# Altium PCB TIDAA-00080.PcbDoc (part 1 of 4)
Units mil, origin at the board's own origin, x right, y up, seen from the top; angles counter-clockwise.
Board outline 7874.02 x 2559.06 mil, 4 copper layers (Top Layer, MidLayer1, MidLayer2, Bottom Layer), stack 61.2 mil thick; 363 components, 169 nets, 940 pads, 199 vias.
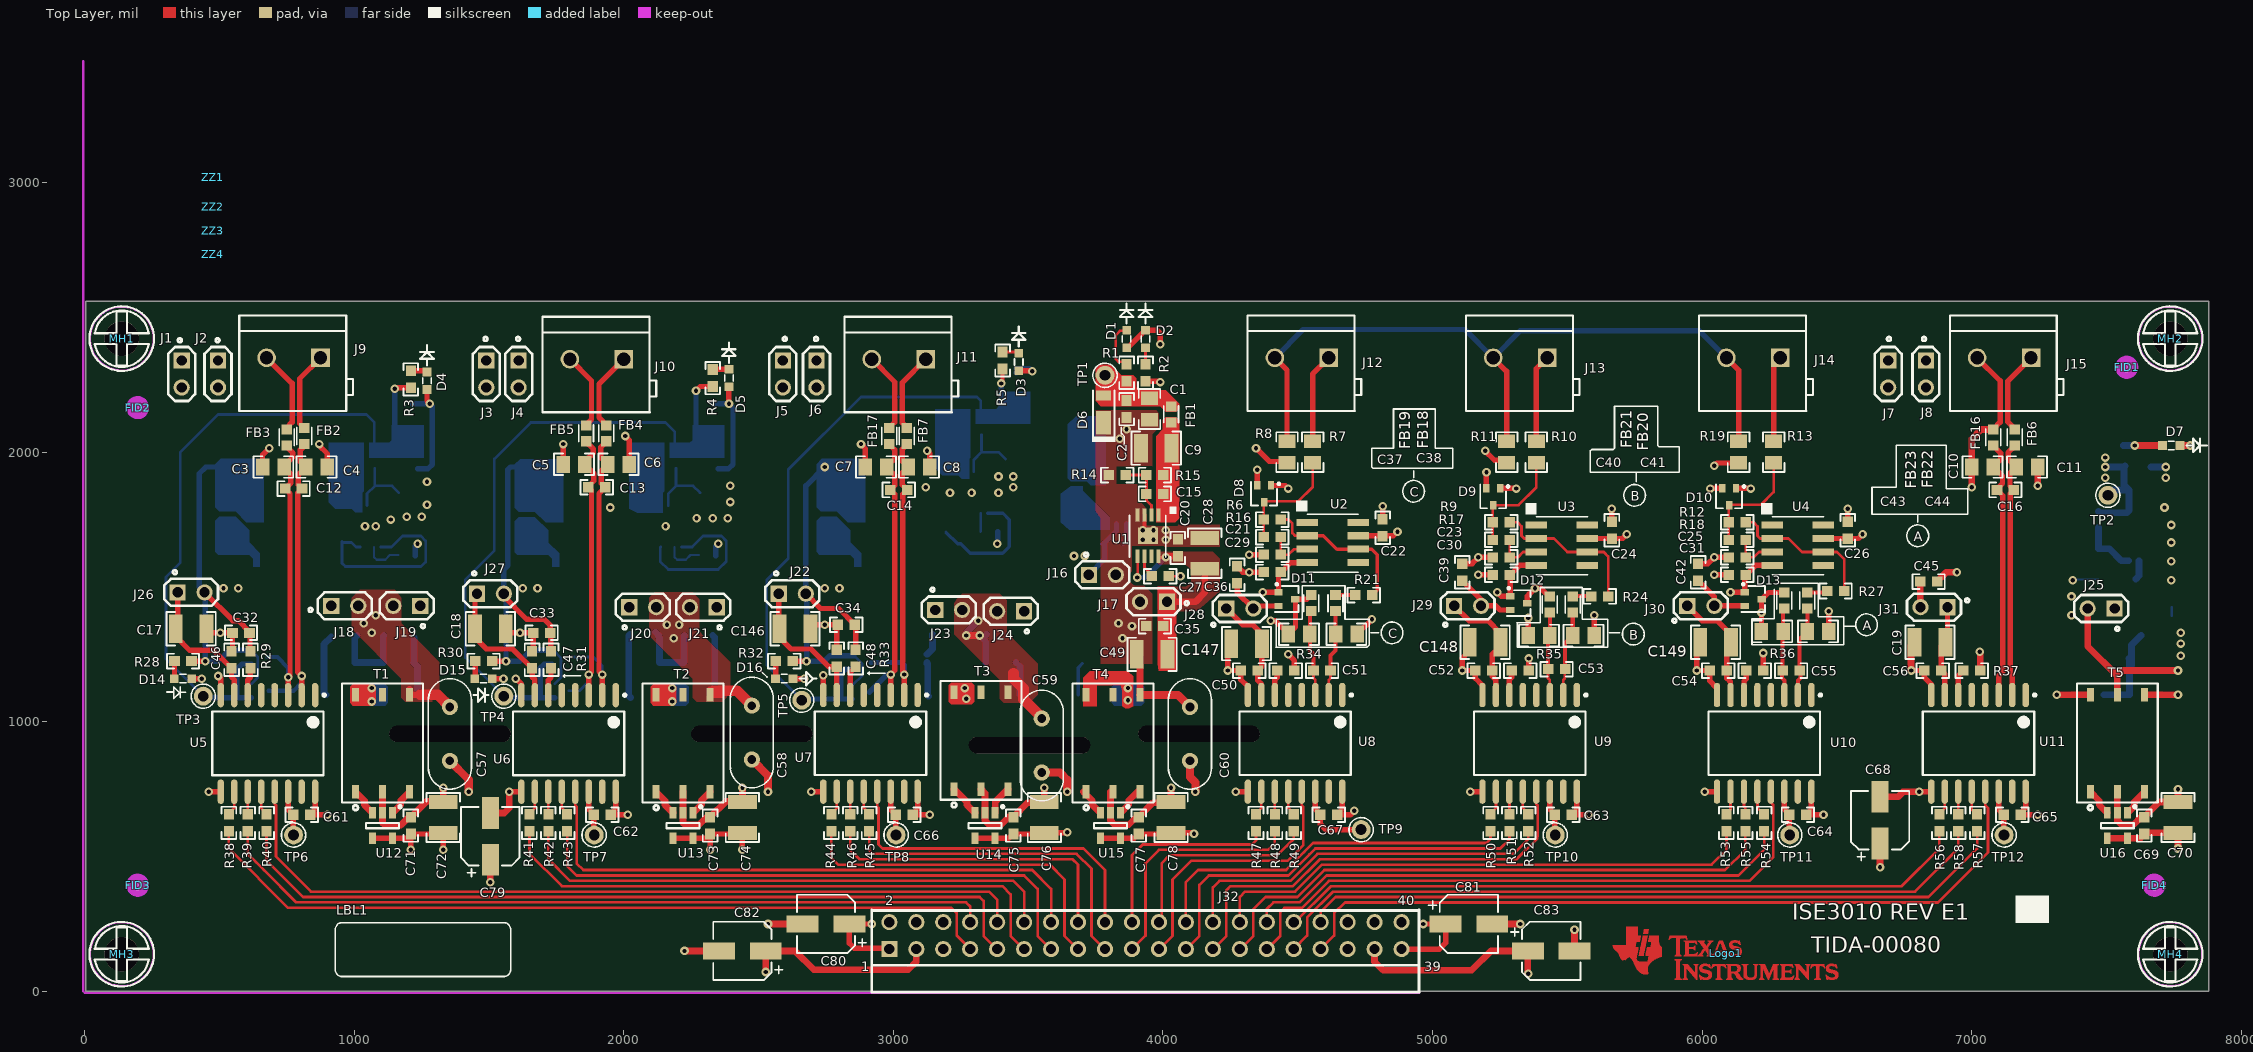
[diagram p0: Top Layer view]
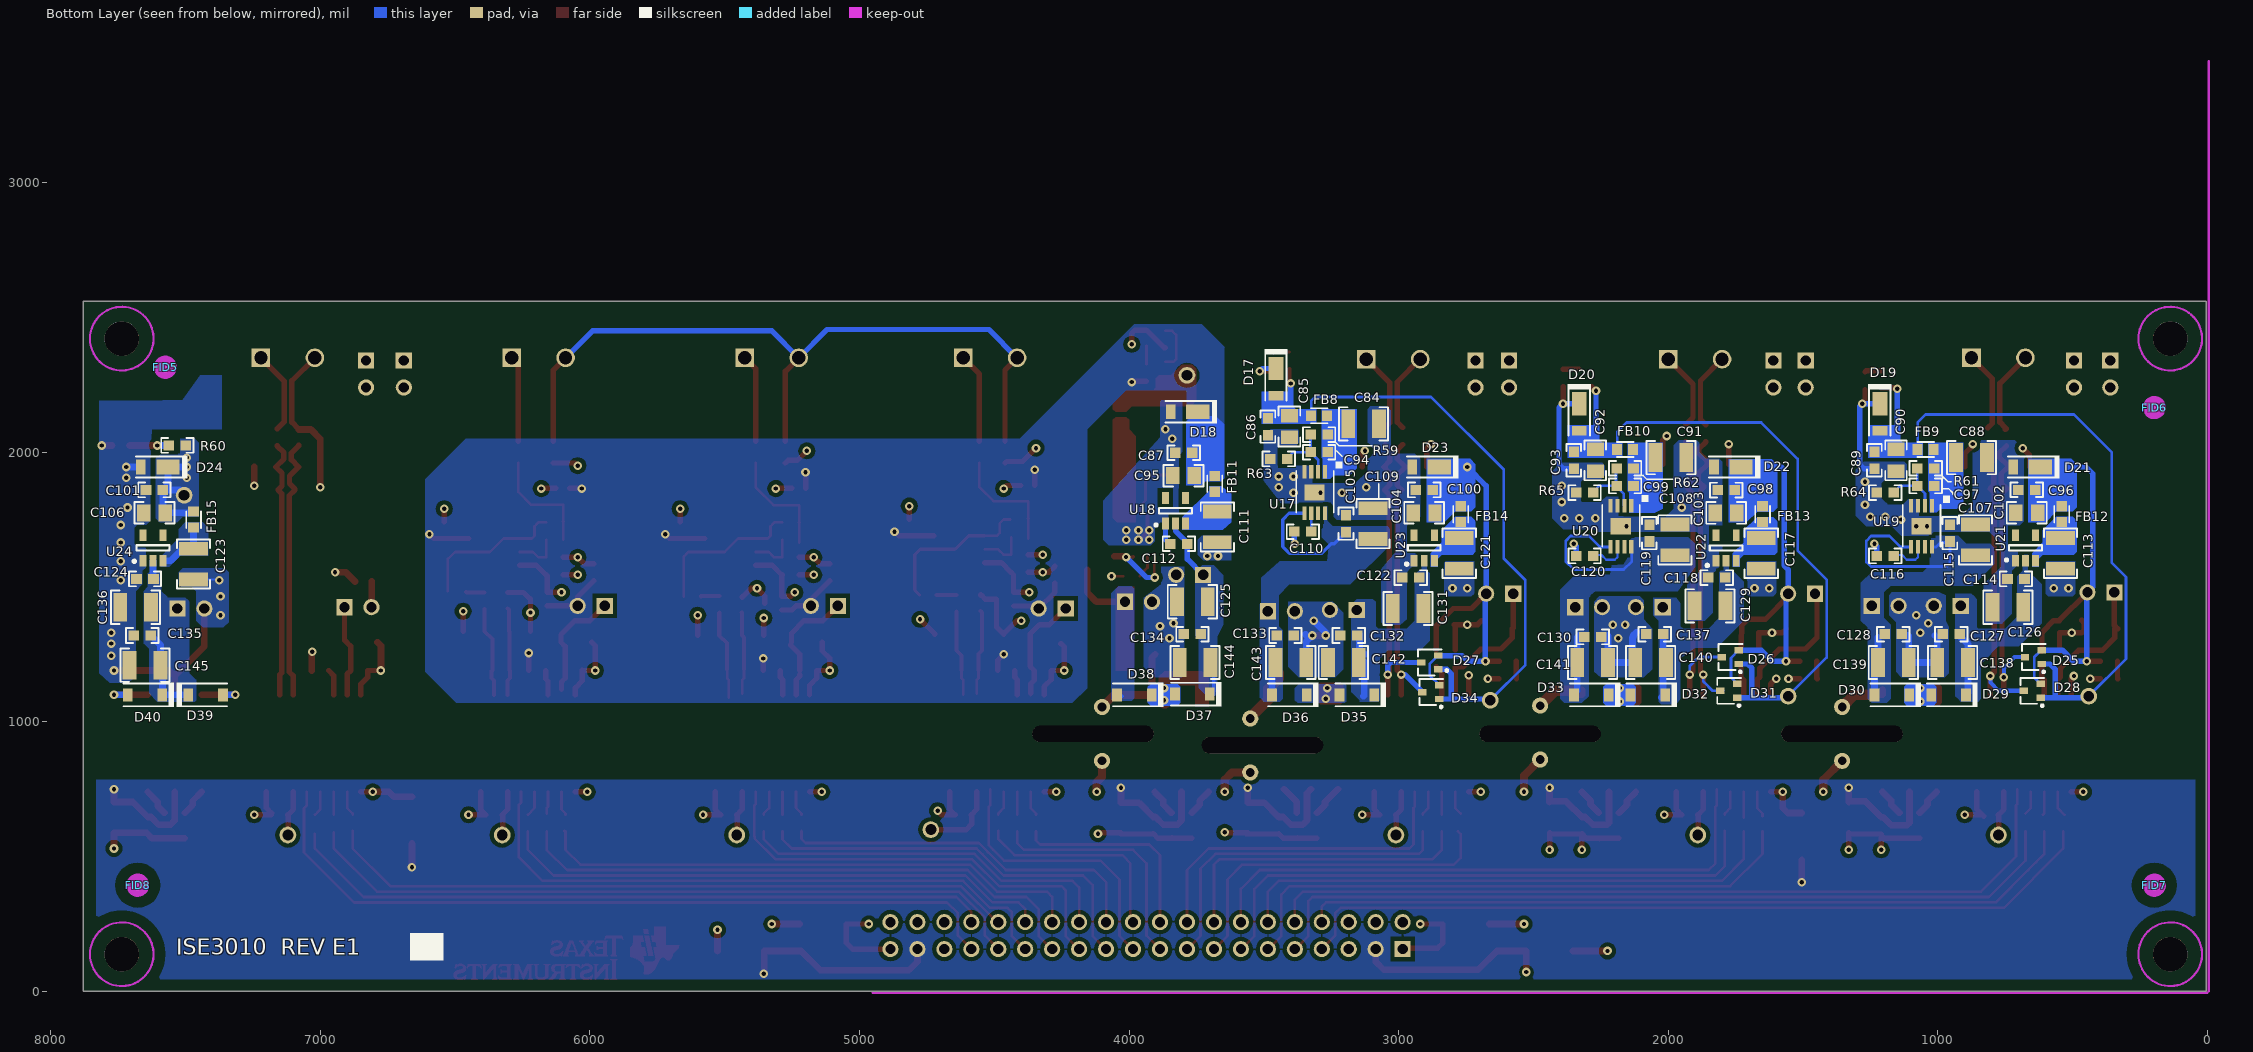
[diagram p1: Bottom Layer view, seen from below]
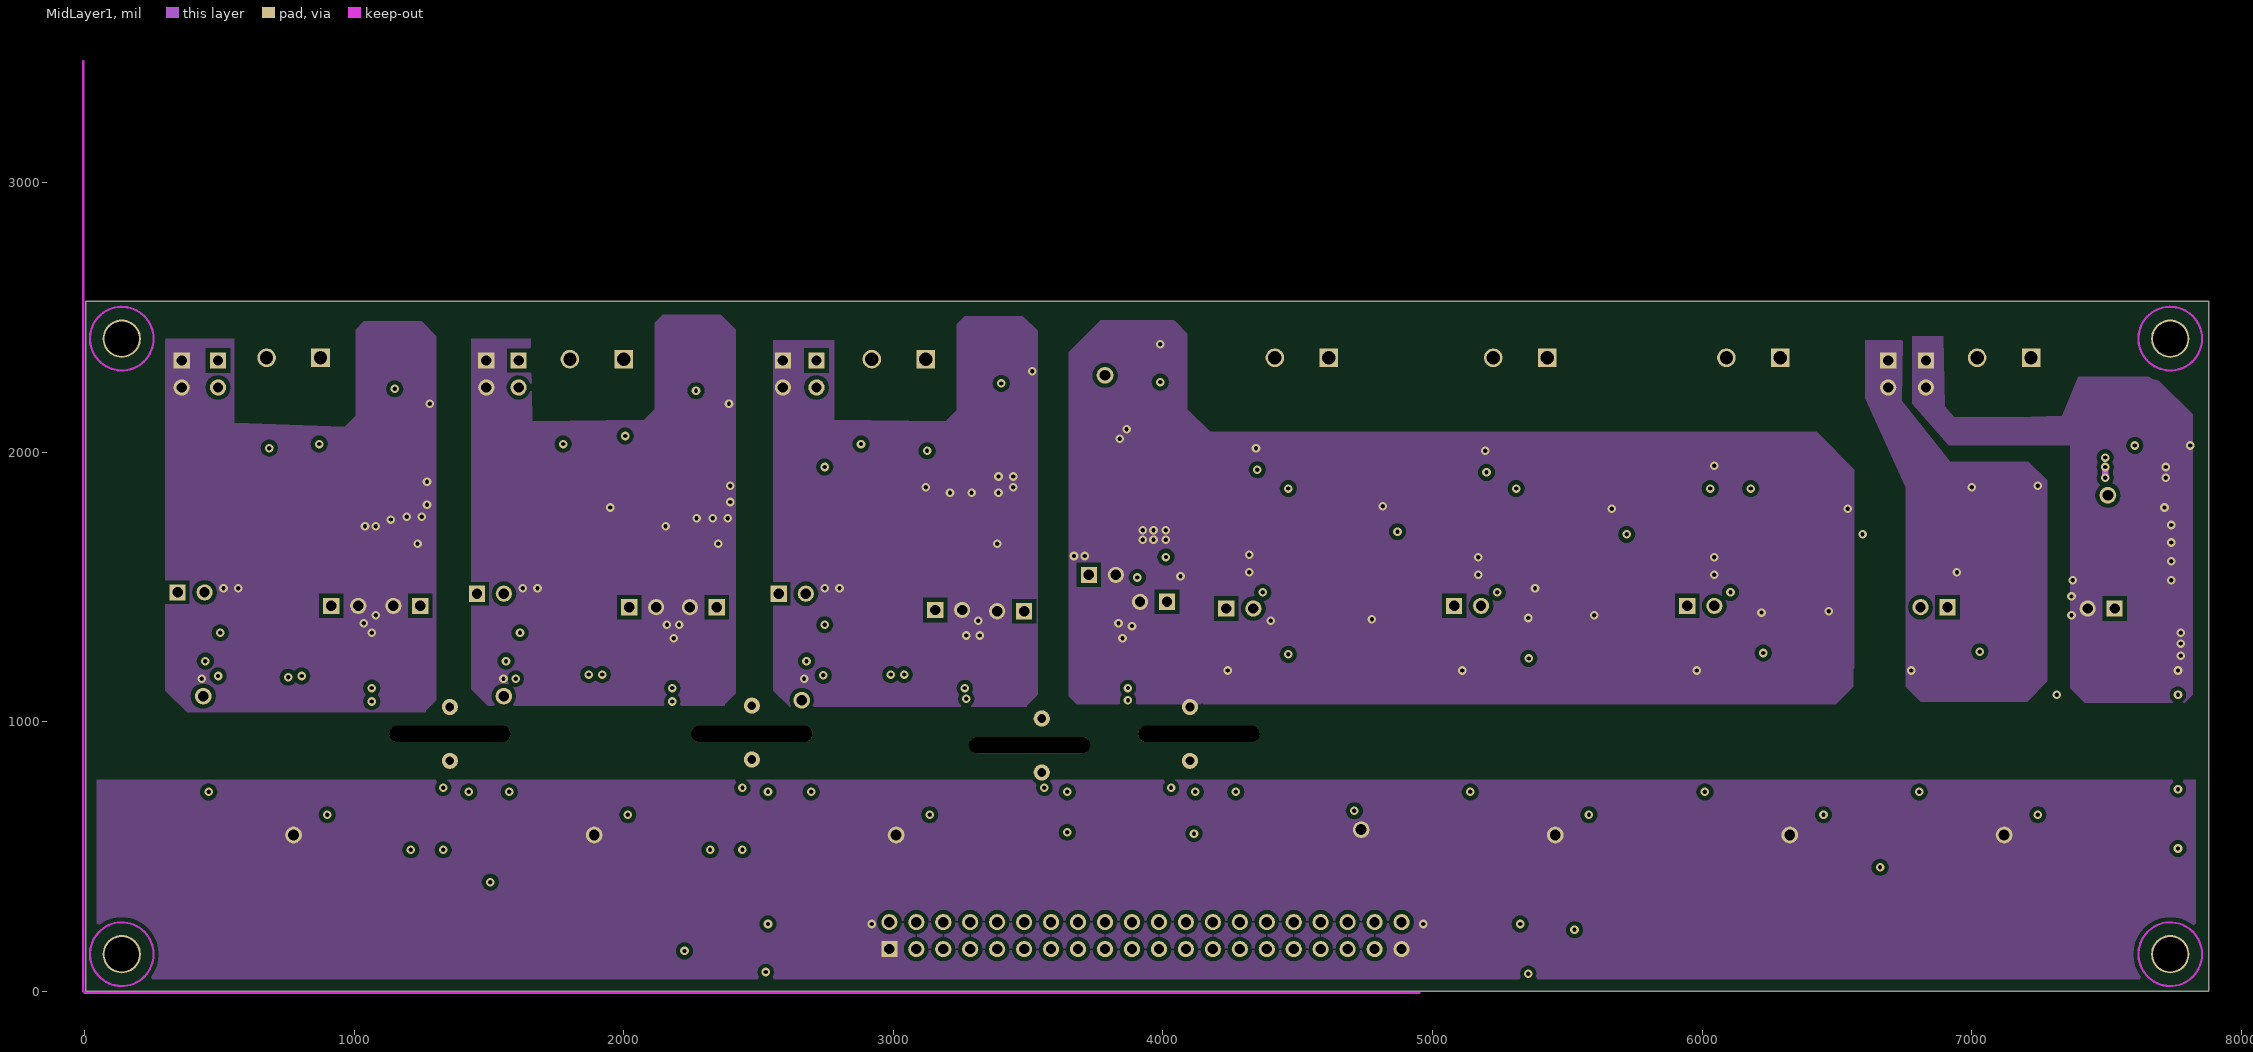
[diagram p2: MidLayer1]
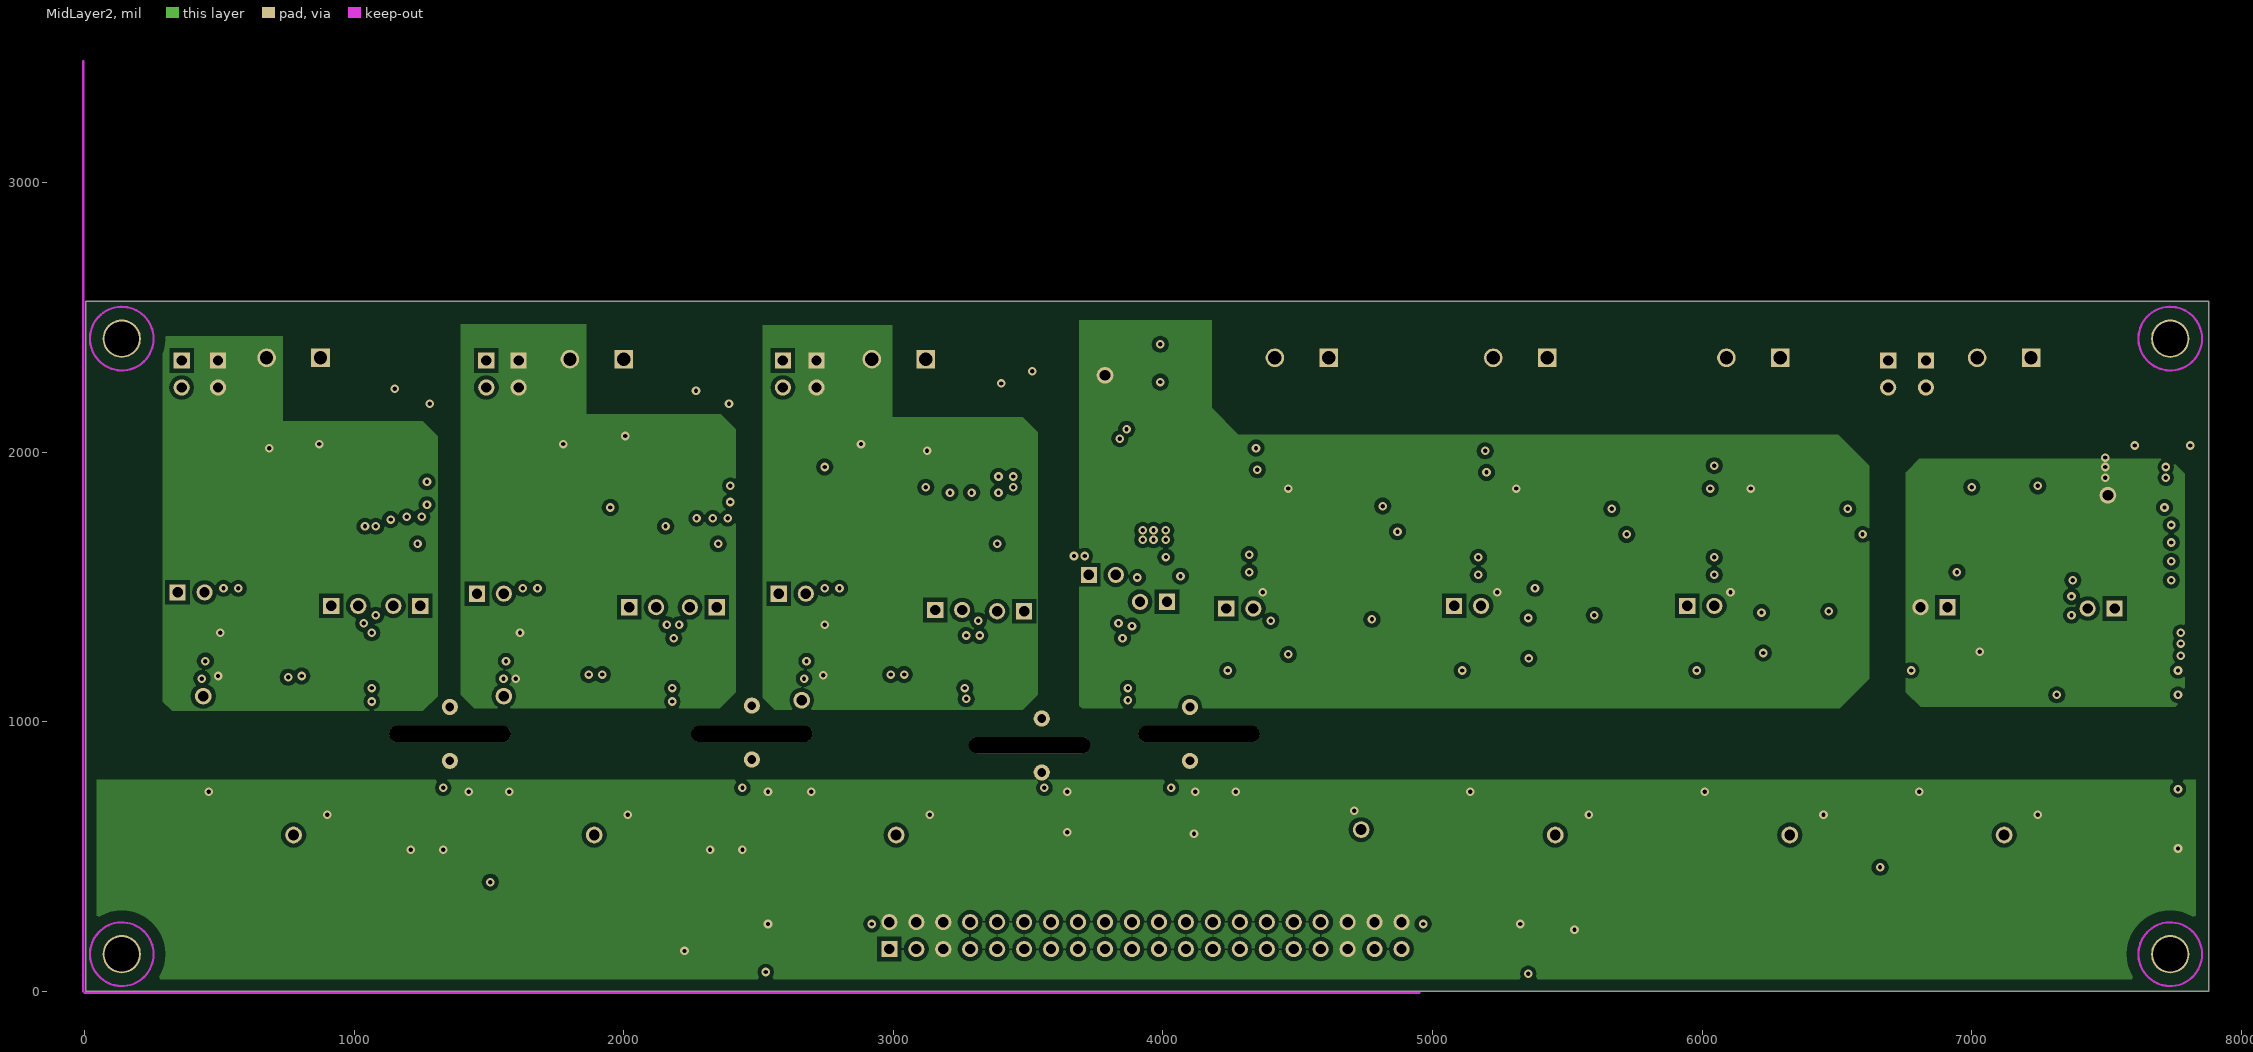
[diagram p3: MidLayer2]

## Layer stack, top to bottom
Top Layer: signal copper 2.8
Dielectric: core 16.6, FR-4, Dk 4.8
MidLayer1: signal copper 2.8
Dielectric: prepreg 16.8, FR-4, Dk 4.8
MidLayer2: signal copper 2.8
Dielectric: core 16.6, FR-4, Dk 4.8
Bottom Layer: signal copper 2.8

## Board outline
5,0 5,2559.06 7879.02,2559.06 7879.02,0

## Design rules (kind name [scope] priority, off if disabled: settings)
AcuteAngle [All] p1 off: minimum=4.50000000000000E+0001 checktracksonly=FALSE
AssemblyTestPointUsage [All] p1 off: valid=2
AssemblyTestpoint [All] p1 off: testpointundercomponent=TRUE minsize=40 maxsize=100 preferedsize=60 minholesize=0 maxholesize=40 preferedholesize=32 testpointgrid=1 usegrid=TRUE gridtolerance=0.01 allowsidetop=TRUE allowsidebottom=TRUE
Clearance Clearance_34 [InNamedPolygon('MidLayer1-No Net 7')] p1: gap=40
Clearance Clearance_33 [InNamedPolygon('MidLayer1-No Net 6')] p2: gap=40
Clearance Clearance_32 [InNamedPolygon('MidLayer1-No Net 5')] p3: gap=40
Clearance Clearance_31 [InNamedPolygon('Top Layer-No Net 6')] p4: gap=40
Clearance Clearance_30 [InNamedPolygon('Top Layer-No Net 5')] p5: gap=40
Clearance Clearance_29 [InNamedPolygon('Top Layer-No Net 4')] p6: gap=40
Clearance Clearance_28 [InNamedPolygon('MidLayer1-No Net 4')] p7: gap=40
Clearance Clearance_27 [InNamedPolygon('MidLayer1-No Net 3')] p8: gap=40
Clearance Clearance_26 [InNamedPolygon('Top Layer-No Net 3')] p9: gap=40
Clearance Clearance_25 [InNamedPolygon('Top Layer-No Net 2')] p10: gap=40
Clearance Clearance_24 [InNamedPolygon('Top Layer-No Net 1')] p11: gap=40
Clearance Clearance_23 [InNamedPolygon('MidLayer1-No Net 2')] p12: gap=40
Clearance Clearance_22 [InNamedPolygon('MidLayer1-No Net 2')] p13: gap=40
Clearance Clearance_21 [InNamedPolygon('MidLayer1-No Net 2')] p14: gap=15
Clearance Clearance_20 [InNamedPolygon('MidLayer1-No Net 2')] p15: gap=40
Clearance Clearance_19 [InNamedPolygon('MidLayer1-No Net 2')] p16: gap=40
Clearance Clearance_18 [InNamedPolygon('MidLayer1-No Net 2')] p17: gap=15
Clearance Clearance_17 [InNamedPolygon('MidLayer1-No Net 2')] p18: gap=40
Clearance Clearance_16 [InNamedPolygon('MidLayer1-No Net 2')] p19: gap=40
Clearance Clearance_15 [InNamedPolygon('MidLayer1-No Net 2')] p20: gap=40
Clearance Clearance_14 [InNamedPolygon('MidLayer1-No Net 2')] p21: gap=40
Clearance Clearance_13 [InNamedPolygon('MidLayer1-No Net 2')] p22: gap=40
Clearance Clearance_12 [InNamedPolygon('MidLayer1-No Net 2')] p23: gap=40
Clearance Clearance_11 [InNamedPolygon('MidLayer1-No Net 2')] p24: gap=40
Clearance Clearance_10 [InNamedPolygon('MidLayer1-No Net 2')] p25: gap=40
Clearance Clearance_9 [InNamedPolygon('MidLayer1-No Net 2')] p26: gap=15
Clearance Clearance_8 [InNamedPolygon('MidLayer1-No Net 2')] p27: gap=40
Clearance Clearance_7 [InNamedPolygon('MidLayer1-No Net 2')] p28: gap=40
Clearance Clearance_6 [InNamedPolygon('MidLayer1-No Net 2')] p29: gap=40
Clearance Clearance_5 [InNamedPolygon('MidLayer1-No Net 2')] p30: gap=40
Clearance Clearance_4 [InNamedPolygon('MidLayer1-No Net')] p31: gap=15
Clearance Clearance_3 [InNamedPolygon('MidLayer1-No Net')] p32: gap=10
Clearance Clearance_2 [InNamedPolygon('MidLayer1-No Net')] p33: gap=10
Clearance Clearance_1 [InNamedPolygon('MidLayer1-No Net')] p34: gap=40
Clearance Clearance_BoardEdge_MountingHoles [OnCopper and InComponentClass('Mounting Holes') vs IsKeepOut] p35: gap=40
Clearance Clearance_BoardEdge_Poly [OnCopper and InPoly vs IsKeepOut] p36: gap=40
Clearance Clearance_BoardEdge [OnCopper and Not InComponentClass('Logo') and not InComponentClass('FiducialMark') and not InRegion(1000,500,4000,800) and Not IsKeepout vs IsKeepOut] p37: gap=40
Clearance Clearance_Poly [InPolygon] p38: gap=15
Clearance [All] p39: gap=8
ComponentClearance ComponentClearance_Logo [InComponentClass('Logo')] p1 off: gap=50 collisioncheckmode=3 verticalgap=10 showdistances=FALSE
ComponentClearance ComponentClearance_ScrewToNut [(HasFootprint('NY PMS 440 0025 PH')) vs (HasFootprint('Keystone_1902C'))] p2 off: gap=5 collisioncheckmode=3 verticalgap=10 showdistances=FALSE
ComponentClearance ComponentClearance_MountingHoles [InComponentClass('Mounting Holes')] p3 off: gap=250 collisioncheckmode=3 verticalgap=100000 showdistances=FALSE
ComponentClearance ComponentClearance_SmallPassives [HasFootprint('0201*') or HasFootprint('0402*') or HasFootprint('0508') or HasFootprint('0603*') or HasFootprint('0612') or HasFootprint('0805*') or HasFootprint('0815*') or HasFootprint('0830*') or HasFootprint('1206*') or HasFootprint('1210*') or HasFootprint('1808*') or HasFootprint('1812*') or HasFootprint('1825*') or HasFootprint('2010*') or HasFootprint('2220*') or HasFootprint('2225*') or HasFootprint('2512*') or HasFootprint('2728*') or HasFootprint('3518*') vs HasFootprint('0201*') or HasFootprint('0402*') or HasFootprint('0508') or HasFootprint('0603*') or HasFootprint('0612') or HasFootprint('0805*') or HasFootprint('0815*') or HasFootprint('0830*') or HasFootprint('1206*') or HasFootprint('1210*') or HasFootprint('1808*') or HasFootprint('1812*') or HasFootprint('1825*') or HasFootprint('2010*') or HasFootprint('2220*') or HasFootprint('2225*') or HasFootprint('2512*') or HasFootprint('2728*') or HasFootprint('3518*')] p4 off: gap=20 collisioncheckmode=3 verticalgap=10 showdistances=FALSE
ComponentClearance ComponentClearance_THtoSMT [IsThruComponent vs IsSMTComponent] p5 off: gap=100 collisioncheckmode=3 verticalgap=30 showdistances=FALSE
ComponentClearance ComponentClearance_THtoTH [IsThruComponent vs IsThruComponent] p6 off: gap=118.11 collisioncheckmode=3 verticalgap=30 showdistances=FALSE
ComponentClearance [All] p7 off: gap=40 collisioncheckmode=3 verticalgap=10 showdistances=FALSE
DiffPairsRouting DiffPair_RS232DiffPairsRouting [InDifferentialPair ('RS232')] p1: maxlimit=8 minlimit=8 mostfreqgap=8 maxuncoupledlength=500
DiffPairsRouting [All] p2: maxlimit=100 minlimit=10 mostfreqgap=10 maxuncoupledlength=1000
FabricationTestPointUsage TestPointUsage [All] p1 off: valid=2 allowmultiple=FALSE
FabricationTestpoint Testpoint [All] p1 off: side=3 testpointundercomponent=TRUE minsize=40 maxsize=100 preferedsize=60 minholesize=0 maxholesize=40 preferedholesize=32 testpointgrid=1 allowsidetop=TRUE allowsidebottom=TRUE usegrid=TRUE gridtolerance=0.01
FanoutControl Fanout_LCC [IsLCC] p1 off: bgadir=Out bgaviamode=Centered fanoutstyle=Auto fanoutdirection=Alternating viagrid=1 // Fanout_LCC (Default Rule)
FanoutControl Fanout_BGA [IsBGA] p2 off: bgadir=Out bgaviamode=Centered fanoutstyle=Auto fanoutdirection=Alternating viagrid=1 // Fanout_BGA (Default Rule)
FanoutControl Fanout_SOIC [IsSOIC] p3 off: bgadir=Out bgaviamode=Centered fanoutstyle=Auto fanoutdirection=Alternating viagrid=1 // Fanout_SOIC (Default Rule)
FanoutControl Fanout_Default [All] p4 off: bgadir=Out bgaviamode=Centered fanoutstyle=Auto fanoutdirection=Alternating viagrid=1 // Fanout_Default (Default Rule)
FanoutControl Fanout_Small [(CompPinCount < 5)] p5 off: bgadir=Out bgaviamode=Centered fanoutstyle=Auto fanoutdirection=OutThenIn viagrid=1 // Fanout_Small (Default Rule)
Height [All] p1 off: minheight=0 maxheight=1000 prefheight=500
HoleSize [All] p1 off: absolutevalues=TRUE maxlimit=251 minlimit=8 maxpercent=80.000 minpercent=20.000
HoleToHoleClearance [All] p1 off: gap=10 allowstackedmicrovias=TRUE
LayerPairs [All] p1 off: enforce=TRUE
MatchedLengths DiffPair_RS232MatchedLengths [InDifferentialPair ('RS232')] p1: tolerance=1000 checknetsindiffpair=TRUE checkdiffpairvsdiffpair=TRUE checkothers=TRUE
MinimumAnnularRing MinimumAnnularRing_ThermalPadVias [IsVia and InAnyComponent] p1 off: minimumring=5.91
MinimumAnnularRing [All] p2 off: minimumring=8
MinimumSolderMaskSliver MinimumSolderMaskSliver_Logo [InComponentClass('Logo') vs InComponentClass('Logo')] p1 off: minsoldermaskwidth=0.7
MinimumSolderMaskSliver [All] p2 off: minsoldermaskwidth=3.94
NetAntennae [All] p1 off: netantennaetolerance=0
PasteMaskExpansion [All] p1 off: expansion=0
PlaneClearance [All] p1: clearance=15
PlaneConnect [All] p1: planeconnectstyle=Direct reliefexpansion=10 reliefentries=4 reliefconductorwidth=10 reliefairgap=10
PolygonConnect [All] p1: connectstyle=Direct reliefconductorwidth=10 reliefentries=4 polygonreliefangle="90 Angle" airgapwidth=10
RoutingCorners [All] p1 off: cornerstyle=45-Degree minsetback=100 maxsetback=100
RoutingLayers [All] p1 off: top layer_v5=TRUE mid layer 1_v5=TRUE mid layer 2_v5=TRUE bottom layer_v5=TRUE
RoutingPriority [All] p1 off: routingpriority=0
RoutingTopology [All] p1 off: topology=Shortest
RoutingVias ThermalPadVias [IsVia and InAnyComponent] p1: holewidth=16 width=32 viastyle="Through Hole" minholewidth=16 minwidth=32 maxholewidth=16 maxwidth=32
RoutingVias [All] p2: holewidth=16 width=32 viastyle="Through Hole" minholewidth=16 minwidth=32 maxholewidth=16 maxwidth=32
SMDToCorner [All] p1 off: distance=30000
SilkToSilkClearance [All] p1 off: silktosilkclearance=5
SilkscreenOverComponentPads [All] p1 off: minsilkscreentomaskgap=5
SolderMaskExpansion [All] p1 off: expansion=1.97
Width DiffPair_RS232Width [InDifferentialPair('RS232')] p1: maxlimit=10 minlimit=10 preferedwidth=10
Width [All] p2: maxlimit=100 minlimit=8 preferedwidth=25 checkconnectedcopper=TRUE
2 further rules are at their usual default settings.

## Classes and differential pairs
component class "Pg3-Current Sense": C3 C4 C5 C6 C7 C8 C10 C11 C12 C13 C14 C16 C17 C18 C19 C32 C33 C34 C45 C46 C47 C48 C56 C61 C62 C65 C66 C80 C81 C82 C83 C146 D25 D26 D27 D28 D31 D34 FB2 FB3 FB4 FB5 FB6 FB7 FB16 FB17 J2 J4 J6 J7 J9 J10 J11 J15 J22 J26 J27 J31 J32 R29 R31 R33 R37 R38 R39 R40 R41 R42 R43 R44 R45 R46 R56 R57 R58 TP6 TP7 TP8 TP12 U5 U6 U7 U11
component class "Mounting Holes": MH1 MH2 MH3 MH4
component class Logo: Logo1
component class Pg7-Hardware: FID1 FID2 FID3 FID4 FID5 FID6 FID7 FID8 LBL1 Logo1 MH1 MH2 MH3 MH4 ZZ1 ZZ2 ZZ3 ZZ4
component class FiducialMark: FID1 FID2 FID3 FID4 FID5 FID6 FID7 FID8
component class AssemblyNote: ZZ1 ZZ2 ZZ3 ZZ4
component class Label: LBL1
component class "Pg5-Power supply 1": C57 C58 C71 C72 C73 C74 C79 C88 C89 C90 C91 C92 C93 C96 C97 C98 C99 C102 C103 C107 C108 C113 C114 C115 C116 C117 C118 C119 C120 C126 C127 C128 C129 C130 C137 C138 C139 C140 C141 D4 D5 D14 D15 D19 D20 D21 D22 D29 D30 D32 D33 FB9 FB10 FB12 FB13 J1 J3 J18 J19 J20 J21 R3 R4 R28 R30 R61 R62 R64 R65 T1 T2 TP3 TP4 U12 U13 U19 U20 U21 U22
component class "Pg6-Power supply 2": C1 C2 C9 C15 C20 C27 C28 C35 C49 C59 C60 C68 C69 C70 C75 C76 C77 C78 C84 C85 C86 C87 C94 C95 C100 C101 C104 C105 C106 C109 C110 C111 C112 C121 C122 C123 C124 C125 C131 C132 C133 C134 C135 C136 C142 C143 C144 C145 D1 D2 D3 D6 D7 D16 D17 D18 D23 D24 D35 D36 D37 D38 D39 D40 FB1 FB8 FB11 FB14 FB15 J5 J8 J16 J17 J23 J24 J25 R1 R2 R5 R14 R15 R32 R59 R60 R63 T3 T4 T5 TP1 TP2 TP5 U1 U14 U15 U16 U17 U18 U23 U24
component class "Pg4-Voltage signal condtioning": C21 C22 C23 C24 C25 C26 C29 C30 C31 C36 C37 C38 C39 C40 C41 C42 C43 C44 C50 C51 C52 C53 C54 C55 C63 C64 C67 C147 C148 C149 D8 D9 D10 D11 D12 D13 FB18 FB19 FB20 FB21 FB22 FB23 J12 J13 J14 J28 J29 J30 R6 R7 R8 R9 R10 R11 R12 R13 R16 R17 R18 R19 R21 R24 R27 R34 R35 R36 R47 R48 R49 R50 R51 R52 R53 R54 R55 TP9 TP10 TP11 U2 U3 U4 U8 U9 U10

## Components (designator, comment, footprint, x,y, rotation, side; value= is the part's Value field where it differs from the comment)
C1 "" 0805_HV 3950,2160 r90 top (schematic designator C84)
C2 "" 0603 3865,2160 r270 top (schematic designator C90)
C3 "GRM21A5C2E470JW01D" 0805_HV 700,1945 r0 top (schematic designator C72)
C4 "GRM21A5C2E470JW01D" 0805_HV 860,1945 r0 top (schematic designator C71)
C5 "GRM21A5C2E470JW01D" 0805_HV 1815,1955 r0 top (schematic designator C74)
C6 "GRM21A5C2E470JW01D" 0805_HV 1980,1955 r0 top (schematic designator C73)
C7 "GRM21A5C2E470JW01D" 0805_HV 2935,1945 r0 top (schematic designator C76)
C8 "GRM21A5C2E470JW01D" 0805_HV 3095,1945 r0 top (schematic designator C75)
C9 "" 1210 3975,2015 r0 top (schematic designator C92)
C10 "GRM21A5C2E470JW01D" 0805_HV 7040,1945 r0 top (schematic designator C79)
C11 "GRM21A5C2E470JW01D" 0805_HV 7205,1945 r0 top (schematic designator C78)
C12 "06031C152KAT2A" 0603 775,1865 r180 top (schematic designator C4)
C13 "06031C152KAT2A" 0603 1900,1870 r180 top (schematic designator C10)
C14 "06031C152KAT2A" 0603 3020,1860 r180 top (schematic designator C77)
C15 "" 0603 3970,1845 r0 top (schematic designator C89)
C16 "06031C152KAT2A" 0603 7125,1860 r180 top (schematic designator C17)
C17 "" 1210 395,1345 r180 top (schematic designator C113)
C18 "" 1210 1505,1345 r180 top (schematic designator C125)
C19 "" 1210 6845,1295 r0 top (schematic designator C137)
C20 "" 0603 4055,1645 r90 top (schematic designator C88)
C21 "" 0603 4405,1620 r180 top (schematic designator C117)
C22 "" 0603 4815,1720 r270 top (schematic designator C111)
C23 "" 0603 5255,1610 r180 top (schematic designator C129)
C24 "" 0603 5665,1710 r270 top (schematic designator C123)
C25 "" 0603 6130,1610 r180 top (schematic designator C141)
C26 "" 0603 6540,1710 r270 top (schematic designator C135)
C27 "" 0603 3990,1540 r180 top (schematic designator C94)
C28 "" 1210 4155,1625 r270 top (schematic designator C83)
C29 "" 0603 4405,1555 r0 top (schematic designator C116)
C30 "" 0603 5255,1545 r0 top (schematic designator C128)
C31 "" 0603 6130,1545 r0 top (schematic designator C140)
C32 "" 0603 580,1330 r180 top (schematic designator C6)
C33 "" 0603 1695,1330 r180 top (schematic designator C12)
C34 "" 0603 2825,1360 r180 top (schematic designator C21)
C35 "" 0603 3970,1355 r0 top (schematic designator C80)
C36 "" 0603 4275,1545 r90 top (schematic designator C121)
C37 "GRM21A5C2E470JW01D" 0805_HV 4505,1325 r0 top (schematic designator C187)
C38 "GRM21A5C2E470JW01D" 0805_HV 4680,1325 r180 top (schematic designator C186)
C39 "" 0603 5110,1555 r90 top (schematic designator C133)
C40 "GRM21A5C2E470JW01D" 0805_HV 5395,1320 r0 top (schematic designator C189)
C41 "GRM21A5C2E470JW01D" 0805_HV 5560,1320 r180 top (schematic designator C188)
C42 "" 0603 5985,1555 r90 top (schematic designator C145)
C43 "GRM21A5C2E470JW01D" 0805_HV 6260,1335 r0 top (schematic designator C194)
C44 "GRM21A5C2E470JW01D" 0805_HV 6430,1335 r180 top (schematic designator C200)
C45 "" 0603 6840,1520 r0 top (schematic designator C19)
C46 "" 0603 545,1230 r90 top (schematic designator C5)
C47 "" 0603 1660,1230 r90 top (schematic designator C11)
C48 "" 0603 2790,1235 r90 top (schematic designator C20)
C49 "" 1210 3960,1250 r0 top (schematic designator C199)
C50 "" 0603 4320,1190 r180 top (schematic designator C120)
C51 "06031C152KAT2A" 0603 4590,1190 r180 top (schematic designator C115)
C52 "" 0603 5190,1190 r180 top (schematic designator C132)
C53 "06031C152KAT2A" 0603 5460,1195 r180 top (schematic designator C127)
C54 "" 0603 6060,1190 r180 top (schematic designator C144)
C55 "06031C152KAT2A" 0603 6330,1190 r180 top (schematic designator C139)
C56 "" 0603 6855,1190 r180 top (schematic designator C18)
C57 "" CAP_200mil#1 1355,955 r90 top (schematic designator C22)
C58 "" CAP_200mil#1 2475,960 r90 top (schematic designator C23)
C59 "" CAP_200mil#1 3550.31,912.01 r90 top (schematic designator C61)
C60 "" CAP_200mil#2 4100,955 r90 top (schematic designator C63)
C61 "" 0603 805,655 r180 top (schematic designator C3)
C62 "" 0603 1920,655 r180 top (schematic designator C7)
C63 "" 0603 5485,655 r180 top (schematic designator C124)
C64 "" 0603 6355,655 r180 top (schematic designator C136)
C65 "" 0603 7150,655 r180 top (schematic designator C13)
C66 "" 0603 3040,655 r180 top (schematic designator C15)
C67 "" 0603 4615,655 r180 top (schematic designator C112)
C68 "UUD1E220MCL1GS" SM_RADIAL_5MM 6660,635 r90 top (schematic designator C64)
C69 "" 0603 7640,615 r90 top
C70 "" 1210 7765,645 r90 top (schematic designator C66)
C71 "" 0603 1210,615 r90 top (schematic designator C26)
C72 "" 1210 1330,645 r90 top (schematic designator C24)
C73 "" 0603 2320,615 r90 top (schematic designator C27)
C74 "" 1210 2440,645 r90 top (schematic designator C25)
C75 "" 0603 3445,615 r90 top (schematic designator C68)
C76 "" 1210 3560,645 r90 top (schematic designator C65)
C77 "" 0603 3910,615 r90 top (schematic designator C70)
C78 "" 1210 4030,645 r90 top (schematic designator C67)
C79 "UUD1E220MCL1GS" SM_RADIAL_5MM 1505,575 r90 top (schematic designator C32)
C80 "UUD1E220MCL1GS" SM_RADIAL_5MM 2750,250 r180 top (schematic designator C1)
C81 "UUD1E220MCL1GS" SM_RADIAL_5MM 5135,250 r0 top (schematic designator C9)
C82 "UUD1E220MCL1GS" SM_RADIAL_5MM 2440,150 r180 top (schematic designator C2)
C83 "UUD1E220MCL1GS" SM_RADIAL_5MM 5440,150 r0 top (schematic designator C8)
C84 "" 1210 3130,2105 r0 bottom (schematic designator C91)
C85 "" 0805_HV 3405,2095 r90 bottom (schematic designator C82)
C86 "" 0603 3485,2095 r270 bottom (schematic designator C87)
C87 "" 0603 3797.4,1997.76 r0 bottom (schematic designator C106)
C88 "" 1210 875,1980 r0 bottom (schematic designator C47)
C89 "" 0603 1235,1970 r270 bottom (schematic designator C43)
C90 "" 0805_HV 1155,1970 r90 bottom (schematic designator C38)
C91 "" 1210 1990,1980 r0 bottom (schematic designator C48)
C92 "" 0805_HV 2270,1970 r90 bottom (schematic designator C40)
C93 "" 0603 2350,1970 r270 bottom (schematic designator C46)
C94 "" 0603 3295,2000 r180 bottom (schematic designator C86)
C95 "" 0805_HV 3797.4,1912.76 r180 bottom (schematic designator C103)
C96 "" 0603 670,1860.32 r0 bottom (schematic designator C53)
C97 "" 0603 1045,1875 r180 bottom (schematic designator C42)
C98 "" 0603 1785,1859.5 r0 bottom (schematic designator C54)
C99 "" 0603 2160,1875 r180 bottom (schematic designator C45)
C100 "" 0603 2905,1860 r0 bottom (schematic designator C97)
C101 "" 0603 7615,1860 r0 bottom (schematic designator C98)
C102 "" 0805_HV 670,1775.32 r180 bottom (schematic designator C51)
C103 "" 0805_HV 1785,1774.5 r180 bottom (schematic designator C52)
C104 "" 0805_HV 2905,1775 r180 bottom (schematic designator C95)
C105 "" 0603 3195,1735 r90 bottom (schematic designator C85)
C106 "" 0805_HV 7615,1775 r180 bottom (schematic designator C96)
C107 "" 1210 860,1675 r270 bottom (schematic designator C37)
C108 "" 1210 1975,1675 r270 bottom (schematic designator C39)
C109 "" 1210 3095,1735 r270 bottom (schematic designator C81)
C110 "" 0603 3355,1705 r180 bottom (schematic designator C93)
C111 "" 1210 3672.4,1722.76 r90 bottom (schematic designator C108)
C112 "" 0603 3815,1660 r0 bottom (schematic designator C109)
C113 "" 1210 545,1625 r90 bottom (schematic designator C56)
C114 "" 0603 710,1530 r0 bottom (schematic designator C59)
C115 "" 0603 955,1700 r90 bottom (schematic designator C41)
C116 "" 0603 1195,1615 r180 bottom (schematic designator C49)
C117 "" 1210 1655,1625 r90 bottom (schematic designator C58)
C118 "" 0603 1820,1535 r0 bottom (schematic designator C60)
C119 "" 0603 2070,1700 r90 bottom (schematic designator C44)
C120 "" 0603 2310,1615 r180 bottom (schematic designator C50)
C121 "" 1210 2775,1625 r90 bottom (schematic designator C100)
C122 "" 0603 2955,1535 r0 bottom (schematic designator C104)
C123 "" 1210 7470,1585 r90 bottom (schematic designator C102)
C124 "" 0603 7650,1530 r0 bottom (schematic designator C105)
C125 "" 1210 3765,1445 r180 bottom (schematic designator C107)
C126 "" 1210 740,1425 r180 bottom (schematic designator C55)
C127 "" 0603 950,1325 r0 bottom (schematic designator C29)
C128 "" 0603 1165,1325 r0 bottom (schematic designator C34)
C129 "" 1210 1845,1430 r180 bottom (schematic designator C57)
C130 "" 0603 2280,1315 r0 bottom (schematic designator C36)
C131 "" 1210 2965,1420 r180 bottom (schematic designator C99)
C132 "" 0603 3185,1320 r0 bottom (schematic designator C191)
C133 "" 0603 3420,1320 r0 bottom (schematic designator C193)
C134 "" 0603 3765,1325 r0 bottom (schematic designator C198)
C135 "" 0603 7660,1320 r0 bottom (schematic designator C196)
C136 "" 1210 7685,1425 r180 bottom (schematic designator C101)
C137 "" 0603 2050,1325 r0 bottom (schematic designator C31)
C138 "" 1210 945,1220 r0 bottom (schematic designator C28)
C139 "" 1210 1165,1220 r0 bottom (schematic designator C33)
C140 "" 1210 2065,1220 r0 bottom (schematic designator C30)
C141 "" 1210 2280,1220 r0 bottom (schematic designator C35)
C142 "" 1210 3205,1220 r0 bottom (schematic designator C190)
C143 "" 1210 3400,1220 r0 bottom (schematic designator C192)
C144 "" 1210 3755,1220 r0 bottom (schematic designator C197)
C145 "" 1210 7650,1210 r0 bottom (schematic designator C195)
C146 "" 1210 2635,1345 r180 top
C147 "" 1210 4310,1290 r0 top
C148 "" 1210 5195,1295 r0 top
C149 "" 1210 6050,1295 r0 top
D1 "" LED0603AA 3865,2420 r270 top (schematic designator D28)
D2 "" LED0603AA 3935,2420 r270 top (schematic designator D34)
D3 "" LED0603AA 3465,2335 r270 top (schematic designator D27)
D4 "" LED0603AA 1270,2265 r270 top (schematic designator D13)
D5 "" LED0603AA 2390,2275 r270 top (schematic designator D14)
D6 "" powerDI123 3780,2160 r90 top (schematic designator D26)
D7 "" LED0603AA 7740,2025 r180 top (schematic designator D33)
D8 "DESD1P0RFW-7" SOT-323 4375,1845 r270 top (schematic designator D84)
D9 "DESD1P0RFW-7" SOT-323 5225,1835 r270 top (schematic designator D85)
D10 "DESD1P0RFW-7" SOT-323 6100,1835 r270 top (schematic designator D83)
D11 "" SOT-323 4460,1455 r0 top (schematic designator D52)
D12 "" SOT-323 5320,1440 r0 top (schematic designator D54)
D13 "" SOT-323 6190,1455 r0 top (schematic designator D53)
D14 "" LED0603AA 365,1160 r180 top (schematic designator D17)
D15 "" LED0603AA 1480,1160 r180 top (schematic designator D18)
D16 "" LED0603AA 2595,1160 r180 top (schematic designator D32)
D17 "" powerDI123 3455,2260 r270 bottom (schematic designator D25)
D18 "" powerDI123 3795,2150 r0 bottom (schematic designator D31)
D19 "" powerDI123 1215,2130 r270 bottom (schematic designator D11)
D20 "" powerDI123 2330,2130 r270 bottom (schematic designator D12)
D21 "" powerDI123 670,1945 r0 bottom (schematic designator D15)
D22 "" powerDI123 1780,1945 r0 bottom (schematic designator D16)
D23 "" powerDI123 2900,1945 r0 bottom (schematic designator D29)
D24 "" powerDI123 7615,1945 r0 bottom (schematic designator D30)
D25 "" SOT-323 645,1240 r0 bottom (schematic designator D2)
D26 "DESD1P0RFW-7" SOT-323 1770,1240 r0 bottom (schematic designator D35)
D27 "DESD1P0RFW-7" SOT-323 2885,1220 r0 bottom (schematic designator D5)
D28 "" SOT-323 650,1115 r0 bottom (schematic designator D1)
D29 "MBR0520L" SOD-123 960,1100 r0 bottom (schematic designator D7)
D30 "MBR0520L" SOD-123 1170,1100 r0 bottom (schematic designator D9)
D31 "DESD1P0RFW-7" SOT-323 1775,1115 r0 bottom (schematic designator D4)
D32 "MBR0520L" SOD-123 2075,1100 r0 bottom (schematic designator D8)
D33 "MBR0520L" SOD-123 2285,1100 r0 bottom (schematic designator D10)
D34 "DESD1P0RFW-7" SOT-323 2880,1110 r0 bottom (schematic designator D6)
D35 "MBR0520L" SOD-123 3155,1100 r0 bottom (schematic designator D19)
D36 "MBR0520L" SOD-123 3405,1100 r0 bottom (schematic designator D23)
D37 "MBR0520L" SOD-123 3765,1102.36 r0 bottom (schematic designator D21)
D38 "MBR0520L" SOD-123 3980,1100 r0 bottom (schematic designator D24)
D39 "MBR0520L" SOD-123 7425,1100 r180 bottom (schematic designator D20)
D40 "MBR0520L" SOD-123 7650,1100 r0 bottom (schematic designator D22)
FB1 "" FB0603 4030,2140 r90 top (schematic designator FB6)
FB2 "MMZ1608B102C" FB0603 815,2060 r270 top (schematic designator FB18)
FB3 "MMZ1608B102C" FB0603 750,2055 r270 top (schematic designator FB17)
FB4 "MMZ1608B102C" FB0603 1935,2070 r270 top (schematic designator FB20)
FB5 "MMZ1608B102C" FB0603 1860,2070 r270 top (schematic designator FB19)
FB6 "MMZ1608B102C" FB0603 7160,2055 r270 top (schematic designator FB22)
FB7 "MMZ1608B102C" FB0603 3050,2060 r270 top (schematic designator FB21)
FB8 "" FB0603 3295,2135 r0 bottom (schematic designator FB5)
FB9 "" FB0603 1045,2010 r0 bottom (schematic designator FB1)
FB10 "" FB0603 2160,2010 r0 bottom (schematic designator FB2)
FB11 "" FB0603 3682.4,1882.76 r90 bottom (schematic designator FB9)
FB12 "" FB0603 540,1770 r90 bottom (schematic designator FB3)
FB13 "" FB0603 1650,1770 r90 bottom (schematic designator FB4)
FB14 "" FB0603 2770,1770 r90 bottom (schematic designator FB7)
FB15 "" FB0603 7470,1750 r90 bottom (schematic designator FB8)
FB16 "MMZ1608B102C" FB0603 7080,2055 r270 top
FB17 "MMZ1608B102C" FB0603 2985,2060 r270 top
FB18 "MMZ1608B102C" FB0603 4640,1440 r270 top
FB19 "MMZ1608B102C" FB0603 4550,1440 r270 top
FB20 "MMZ1608B102C" FB0603 5520,1435 r270 top
FB21 "MMZ1608B102C" FB0603 5435,1435 r270 top
FB22 "MMZ1608B102C" FB0603 6390,1450 r270 top
FB23 "MMZ1608B102C" FB0603 6305,1450 r270 top
FID1 "" Fiducial10-20 7575,2315 r90 top (schematic designator FID4)
FID2 "" Fiducial10-20 196.85,2165.35 r0 top (schematic designator FID1)
FID3 "" Fiducial10-20 196.85,393.7 r0 top (schematic designator FID2)
FID4 "" Fiducial10-20 7677.17,393.7 r0 top (schematic designator FID3)
FID5 "" Fiducial10-20 7575,2315 r180 bottom (schematic designator FID7)
FID6 "" Fiducial10-20 196.85,2165.35 r180 bottom (schematic designator FID8)
FID7 "" Fiducial10-20 196.85,393.7 r180 bottom (schematic designator FID5)
FID8 "" Fiducial10-20 7677.17,393.7 r180 bottom (schematic designator FID6)
J1 "" HDR100_1X2 360,2340 r270 top (schematic designator J31)
J2 "" HDR100_1X2 495,2340 r270 top (schematic designator J14)
J3 "" HDR100_1X2 1490,2340 r270 top (schematic designator J32)
J4 "" HDR100_1X2 1610,2340 r270 top (schematic designator J16)
J5 "" HDR100_1X2 2590,2340 r270 top (schematic designator J45)
J6 "" HDR100_1X2 2715,2340 r270 top (schematic designator J18)
J7 "" HDR100_1X2 6690,2340 r270 top (schematic designator J34)
J8 "" HDR100_1X2 6830,2340 r270 top (schematic designator J46)
J9 "ED120/2DS" CONN_ED120-2DS 775,2350 r90 top (schematic designator J13)
J10 "ED120/2DS" CONN_ED120-2DS 1900,2345 r90 top (schematic designator J15)
J11 "ED120/2DS" CONN_ED120-2DS 3020,2345 r90 top (schematic designator J17)
J12 "ED120/2DS" CONN_ED120-2DS 4515,2350 r90 top (schematic designator J20)
J13 "ED120/2DS" CONN_ED120-2DS 5325,2350 r90 top (schematic designator J21)
J14 "ED120/2DS" CONN_ED120-2DS 6190,2350 r90 top (schematic designator J22)
J15 "ED120/2DS" CONN_ED120-2DS 7120,2350 r90 top (schematic designator J33)
J16 "" HDR100_1X2 3725,1545 r0 top (schematic designator J19)
J17 "" HDR100_1X2 4015,1445 r180 top (schematic designator J41)
J18 "" HDR100_1X2 915,1430 r0 top (schematic designator J38)
J19 "" HDR100_1X2 1245,1430 r180 top (schematic designator J11)
J20 "" HDR100_1X2 2020,1425 r0 top (schematic designator J39)
J21 "" HDR100_1X2 2345,1425 r180 top (schematic designator J12)
J22 "" HDR100_1X2 2575,1475 r0 top (schematic designator J10)
J23 "" HDR100_1X2 3155,1415 r0 top (schematic designator J42)
J24 "" HDR100_1X2 3485,1410 r180 top (schematic designator J40)
J25 "" HDR100_1X2 7530,1420 r180 top (schematic designator J43)
J26 "" HDR100_1X2 345,1480 r0 top (schematic designator J24)
J27 "" HDR100_1X2 1455,1475 r0 top (schematic designator J5)
J28 "" HDR100_1X2 4235,1420 r0 top (schematic designator J49)
J29 "" HDR100_1X2 5080,1430 r0 top (schematic designator J44)
J30 "" HDR100_1X2 5945,1430 r0 top (schematic designator J48)
J31 "" HDR100_1X2 6910,1425 r180 top (schematic designator J9)
J32 "2-826634-0" CONN_61304021021 3937.01,206.69 r180 top (schematic designator J1)
LBL1 "" Label_650x200 1255,155 r180 top
Logo1 "" TI_Stacked_SolderMask_Small 6087,141 r0 top
MH1 "" MH3.2 137.8,2421.26 r0 top
MH2 "" MH3.2 7736.22,2421.26 r0 top (schematic designator MH3)
MH3 "" MH3.2 137.8,137.8 r0 top locked (schematic designator MH4)
MH4 "" MH3.2 7736.22,137.8 r0 top locked (schematic designator MH2)
R1 "" 0603 3865,2295 r270 top (schematic designator R43)
R2 "" 0603 3935,2295 r270 top (schematic designator R50)
R3 "" 0603 1210,2270 r270 top (schematic designator R34)
R4 "" 0603 2330,2275 r270 top (schematic designator R35)
R5 "" 0603 3405,2340 r270 top (schematic designator R42)
R6 "CRCW06030000Z0EA" 0603 4405,1750 r0 top (schematic designator R99)
R7 "CRCW08050000Z0EA" 0805_HV 4555,2000 r270 top (schematic designator R89)
R8 "CRCW08050000Z0EA" 0805_HV 4460,2000 r270 top (schematic designator R101)
R9 "CRCW06030000Z0EA" 0603 5255,1740 r0 top (schematic designator R100)
R10 "CRCW08050000Z0EA" 0805_HV 5385,2000 r270 top (schematic designator R105)
R11 "CRCW08050000Z0EA" 0805_HV 5275,2000 r270 top (schematic designator R102)
R12 "CRCW06030000Z0EA" 0603 6130,1740 r0 top (schematic designator R127)
R13 "CRCW08050000Z0EA" 0805_HV 6265,2000 r270 top (schematic designator R106)
R14 "" 0603 3830,1915 r0 top (schematic designator R47)
R15 "" 0603 3970,1915 r0 top (schematic designator R45)
R16 "" 0603 4405,1685 r0 top (schematic designator R64)
R17 "" 0603 5255,1675 r0 top (schematic designator R88)
R18 "" 0603 6130,1675 r0 top (schematic designator R132)
R19 "CRCW08050000Z0EA" 0805_HV 6135,2000 r270 top (schematic designator R115)
R21 "" 0603 4745,1470 r180 top (schematic designator R59)
R24 "" 0603 5620,1465 r180 top (schematic designator R83)
R27 "" 0603 6495,1485 r180 top (schematic designator R128)
R28 "" 0603 365,1225 r0 top (schematic designator R40)
R29 "" 0603 615,1230 r270 top (schematic designator R6)
R30 "" 0603 1480,1225 r0 top (schematic designator R41)
R31 "" 0603 1730,1230 r270 top (schematic designator R14)
R32 "" 0603 2595,1225 r0 top (schematic designator R48)
R33 "" 0603 2860,1235 r270 top (schematic designator R31)
R34 "" 0603 4455,1190 r180 top (schematic designator R72)
R35 "" 0603 5325,1190 r180 top (schematic designator R96)
R36 "" 0603 6195,1190 r180 top (schematic designator R180)
R37 "" 0603 7000,1190 r180 top (schematic designator R26)
R38 "" 0603 535,625 r270 top (schematic designator R8)
R39 "" 0603 605,625 r270 top (schematic designator R7)
R40 "" 0603 675,625 r270 top (schematic designator R5)
R41 "" 0603 1650,625 r270 top (schematic designator R16)
R42 "" 0603 1720,625 r270 top (schematic designator R15)
R43 "" 0603 1790,625 r270 top (schematic designator R13)
R44 "" 0603 2770,625 r270 top (schematic designator R33)
R45 "" 0603 2910,625 r270 top (schematic designator R30)
R46 "" 0603 2840,625 r270 top (schematic designator R32)
R47 "" 0603 4345,625 r270 top (schematic designator R74)
R48 "" 0603 4415,625 r270 top (schematic designator R73)
R49 "" 0603 4485,625 r270 top (schematic designator R69)
R50 "" 0603 5215,625 r270 top (schematic designator R98)
R51 "" 0603 5285,625 r270 top (schematic designator R97)
R52 "" 0603 5355,625 r270 top (schematic designator R93)
R53 "" 0603 6090,625 r270 top (schematic designator R122)
R54 "" 0603 6230,625 r270 top (schematic designator R117)
R55 "" 0603 6160,625 r270 top (schematic designator R141)
R56 "" 0603 6880,625 r270 top (schematic designator R28)
R57 "" 0603 7020,625 r270 top (schematic designator R25)
R58 "" 0603 6950,625 r270 top (schematic designator R27)
R59 "" 0603 3295,2065 r180 bottom (schematic designator R44)
R60 "" 0603 7530,2025 r180 bottom (schematic designator R49)
R61 "" 0603 1045,1940 r180 bottom (schematic designator R36)
R62 "" 0603 2160,1940 r180 bottom (schematic designator R37)
R63 "" 0603 3445,1975 r180 bottom (schematic designator R46)
R64 "" 0603 1195,1850 r180 bottom (schematic designator R38)
R65 "" 0603 2310,1850 r180 bottom (schematic designator R39)
T1 "750342271" 760390015 1005,740 r90 top
T2 "750342271" 760390015 2120,740 r90 top
T3 "750342271" 760390015 3225,750 r90 top
T4 "750342271" 760390015 3715,740 r90 top (schematic designator T5)
T5 "750342271" 760390015 7440,740 r90 top (schematic designator T4)
TP1 "" TP-040_RND 3785,2285 r0 top (schematic designator TP8)
TP2 "" TP-040_RND 7505,1840 r0 top (schematic designator TP9)
TP3 "" TP-040_RND 440,1095 r90 top (schematic designator TP5)
TP4 "" TP-040_RND 1555,1095 r90 top (schematic designator TP6)
TP5 "" TP-040_RND 2660,1080 r90 top (schematic designator TP7)
TP6 "" TP-040_RND 775,580 r0 top (schematic designator TP1)
TP7 "" TP-040_RND 1890,580 r0 top (schematic designator TP2)
TP8 "" TP-040_RND 3010,580 r0 top (schematic designator TP4)
TP9 "" TP-040_RND 4735,600 r0 top (schematic designator TP10)
TP10 "" TP-040_RND 5455,580 r90 top (schematic designator TP11)
TP11 "" TP-040_RND 6325,580 r180 top (schematic designator TP12)
TP12 "" TP-040_RND 7120,580 r90 top (schematic designator TP3)
U1 "" MSOP8(DGN) 3945,1690 r270 top (schematic designator U15)
U2 "OPA211ID" SO8 4630,1665 r0 top (schematic designator U20)
U3 "OPA211ID" SO8 5480,1655 r0 top locked (schematic designator U23)
U4 "OPA211ID" SO8 6355,1655 r0 top (schematic designator U26)
U5 "AMC1304M25" DW0016A_N 680,919.69 r270 top (schematic designator U1)
U6 "AMC1304M25" DW0016A_N 1795,919.68 r270 top (schematic designator U2)
U7 "AMC1304M25" DW0016A_N 2915,920 r270 top (schematic designator U4)
U8 "AMC1304M25" DW0016A_N 4490,920 r270 top (schematic designator U21)
U9 "AMC1304M25" DW0016A_N 5360,920 r270 top (schematic designator U24)
U10 "AMC1304M25" DW0016A_N 6230,920 r270 top (schematic designator U27)
U11 "AMC1304M25" DW0016A_N 7025,920 r270 top (schematic designator U3)
U12 "SN6501DBV" DBV0005A_N 1105,615 r270 top (schematic designator U5)
U13 "SN6501DBV" DBV0005A_N 2220,615 r270 top (schematic designator U6)
U14 "SN6501DBV" DBV0005A_N 3340,615 r270 top (schematic designator U11)
U15 "SN6501DBV" DBV0005A_N 3805,615 r270 top (schematic designator U13)
U16 "SN6501DBV" DBV0005A_N 7540,615 r270 top (schematic designator U12)
U17 "" MSOP8(DGN) 3310.8,1850 r270 bottom (schematic designator U14)
U18 "TLV70450DBV" DBV0005A_N 3827.4,1782.76 r90 bottom
U19 "TPS7A3001DGNR" MSOP8(DGN) 1060,1725 r270 bottom (schematic designator U7)
U20 "" MSOP8(DGN) 2175,1725 r270 bottom (schematic designator U8)
U21 "TLV70450DBV" DBV0005A_N 675,1645 r90 bottom (schematic designator U9)
U22 "TLV70450DBV" DBV0005A_N 1785,1644.5 r90 bottom (schematic designator U10)
U23 "TLV70450DBV" DBV0005A_N 2905,1645 r90 bottom (schematic designator U16)
U24 "TLV70450DBV" DBV0005A_N 7620,1645 r90 bottom (schematic designator U17)
ZZ1 "" AssemblyNoteLabel 475.78,3019.63 r0 top
ZZ2 "" AssemblyNote 475.78,2910.75 r0 top
ZZ3 "" AssemblyNote 475.78,2822.19 r0 top
ZZ4 "" AssemblyNote 475.78,2733.63 r0 top

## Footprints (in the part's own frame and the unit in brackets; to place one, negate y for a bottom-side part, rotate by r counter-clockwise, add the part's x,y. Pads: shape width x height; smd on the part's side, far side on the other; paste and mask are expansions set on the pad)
0603 [mm] "0603 from SM-752 data"
  rect 1x0.95 smd: 1(-0.8,0) 2(0.8,0)
  silkscreen extent -1.52,-0.69 1.52,0.69, body extent -0.87,-0.47 0.87,0.47, height 0.85
0805_HV [mil] "0805 with 30mil clearance between pads"
  rect 50x63 smd: 1(-40,0) 2(40,0)
  silkscreen extent -74,-40 74,40, body extent -43,-29 43,29, height 43
1210 [mm] "1210 from SM-752 data"
  rect 1.3x2.7 smd: 1(-1.45,0) 2(1.45,0)
  silkscreen extent -2.32,-1.57 2.32,1.57, body extent -1.7,-1.35 1.7,1.35, height 1.35
760390015 [mm]
  rect 1.27x0.66 smd: 1(0,0) 2(0,-2.54) 3(0,-5.08) 4(9.14,-5.08) 5(9.14,-2.54) 6(9.14,0)
  silkscreen extent -1.72,-6.35 10.2,1.27, body extent -1,-6.4 10.2,1.2, height 4.2
AssemblyNote [mil] "Assembly Note"
AssemblyNoteLabel [mil] "Assembly Note for PCB Labels"
CAP_200mil#1 [mil]
  round 60 hole 32 mask+5: 1(-100,0) 2(100,0)
  silkscreen extent -205,-80 205,80
CAP_200mil#2 [mil]
  round 60 hole 32 mask+5: 1(-100,0)
  round 60 hole 32 mask+4: 2(100,0)
  silkscreen extent -205,-80 205,80
CONN_61304021021 [mil]
  rect 60x60 hole 38: 1(952,50)
  round 60 hole 38: 2(952,-50) 3(852,50) 4(852,-50) 5(752,50) 6(752,-50) 7(652,50) 8(652,-50) 9(552,50) 10(552,-50) 11(452,50) 12(452,-50) 13(352,50) 14(352,-50) 15(252,50) 16(252,-50) 17(152,50) 18(152,-50) 19(52,50) 20(52,-50) 21(-48,50) 22(-48,-50) 23(-148,50) 24(-148,-50) 25(-248,50) 26(-248,-50) 27(-348,50) 28(-348,-50) 29(-448,50) 30(-448,-50) 31(-548,50) 32(-548,-50) 33(-648,50) 34(-648,-50) 35(-748,50) 36(-748,-50) 37(-848,50) 38(-848,-50) 39(-948,50) 40(-948,-50)
CONN_ED120-2DS [mm] "ONSHORE"
  rect 1.75x1.75 hole 1.25: 1(0,-2.54)
  round 1.75 hole 1.25: 2(0,2.54)
  silkscreen extent -5,-5.6 4,5.12, body extent -5,-5.6 4.15,5.12, height 13.1
DBV0005A_N [mm] "SOT23, 5-Leads, Body 2.9x1.6mm, Pitch 0.95mm, Lead Span 2.8mm, IPC Medium Density"
  rect 1.1x0.65 smd: 1(-1.2,0.95) 2(-1.2,0) 3(-1.2,-0.95) 4(1.2,-0.95) 5(1.2,0.95)
  silkscreen extent -1.9,-1.55 0.25,1.78, body extent -1.42,-1.46 1.42,1.46, height 1.08
DW0016A_N [mm] "SOIC, 16-Leads, Body 10.3x7.5mm, Pitch 1.27mm, IPC Medium Density"
  oval 2.3x0.6 smd: 1(-4.55,4.445) 2(-4.55,3.175) 3(-4.55,1.905) 4(-4.55,0.635) 5(-4.55,-0.635) 6(-4.55,-1.905) 7(-4.55,-3.175) 8(-4.55,-4.445) 9(4.55,-4.445) 10(4.55,-3.175) 11(4.55,-1.905) 12(4.55,-0.635) 13(4.55,0.635) 14(4.55,1.905) 15(4.55,3.175) 16(4.55,4.445)
  silkscreen extent -4.67,-5.25 3,5.42, body extent -3.79,-5.25 3.8,5.25, height 2.64
FB0603 [mm]
  rect 0.95x1 smd: 1(-0.75,0) 2(0.75,0)
  silkscreen extent -0.8,-0.7 0.8,0.7
Fiducial10-20 [mm]
  round 1 smd paste+0 mask+0.5: 1(0,0)
  Top Layer keep-out circle w1.178: c0,0 r0.5
HDR100_1X2 [mil]
  rect 60x60 hole 38: 1(0,0)
  round 60 hole 38: 2(100,0)
  silkscreen extent -82,-50 150,50
Label_650x200 [mil] "Thermal Transfer Label"
  round 1 on Mech13: 0(0,0)
  silkscreen extent -325,-100 325,100, body extent -326,-101 326,101, height 1
LED0603AA [mil]
  rect 32x32 smd: 1(-32.48,0) 2(32.48,0)
  silkscreen extent -132,-25 11,25
MH3.2 [mil]
  round 128 / inner round 142 / far side round 128 hole 128 unplated mask+10: 1(0,0)
  silkscreen extent -120,-120 120,120
MSOP8(DGN) [mil]
  rect 50x15 smd mask+3: 1(-77,38) 2(-77,12.4) 3(-77,-13.2) 4(-77,-38.8) 5(76.6,-38.8) 6(76.6,-13.2) 7(76.6,12.4) 8(76.6,38)
  rect 60x75 smd: 9(0,-0.8)
  silkscreen extent -108,80 -83,105
powerDI123 [mm] "Diodes Inc recommended land pattern, document number DS30628 Rev. 6-2"
  rect 2.2x1.4 smd: 1(-1.275,0)
  rect 0.9x1.4 smd: 2(1.275,0)
  silkscreen extent -3.1,-1.09 1.76,1.09, body extent -2.38,-0.97 1.52,0.96, height 1
SM_RADIAL_5MM [mm] "Nichicon 5x5.8"
  rect 3x1.6 smd: 1(-2.2,0) 2(2.2,0)
  silkscreen extent -3.81,-2.75 2.75,2.75, body extent -2.75,-2.75 2.75,2.75, height 6.1
SO8 [mil]
  rect 80x26 smd: 1(-95,75) 2(-95,25) 3(-95,-25) 4(-95,-75) 5(94,-75) 6(94,-25) 7(94,25) 8(94,75)
  silkscreen extent -135,115 -95,155
SOD-123 [mm] "On Semi recommended land pattern"
  rect 0.915x1.22 smd: 1(-1.637,0) 2(1.637,0)
  silkscreen extent -2.74,-1.17 2.03,1.17, body extent -1.93,-0.9 1.93,0.9, height 1.35
SOT-323 [mm] "Zetex recommended land pattern.  March 2007"
  rect 0.8x0.6 smd: 1(-0.8,0.65) 2(-0.8,-0.65) 3(0.8,0)
  silkscreen extent -1.14,-1.22 1.09,1.49, body extent -1.13,-1.13 1.12,1.12, height 1.13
